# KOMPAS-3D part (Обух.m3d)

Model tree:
1. Эскиз:1
2. Операция выдавливания:1
     Расстояние 1 = 150; Расстояние 2 = 16
3. Эскиз:2
4. Вырезать элемент выдавливания:2
     Расстояние 1 = 110
5. Скругление:3
     Радиус = 20
6. Скругление:4
     Радиус = 20
7. Эскиз:3
8. Операция выдавливания:2
     Расстояние 1 = 10
9. Скругление:6
     Радиус = 3
10. Скругление:7
     Радиус = 3
11. Скругление:8
     Радиус = 3
12. Скругление:9
     Радиус = 1
13. Скругление:10
     Радиус = 1
14. Скругление:11
     Радиус = 1
15. Скругление:12
     Радиус = 3
16. Скругление:13
     Радиус = 2
17. Скругление:14
     Радиус = 2
18. Скругление:15
     Радиус = 2
19. Скругление:16
     Радиус = 2
20. Скругление:17
     Радиус = 2
